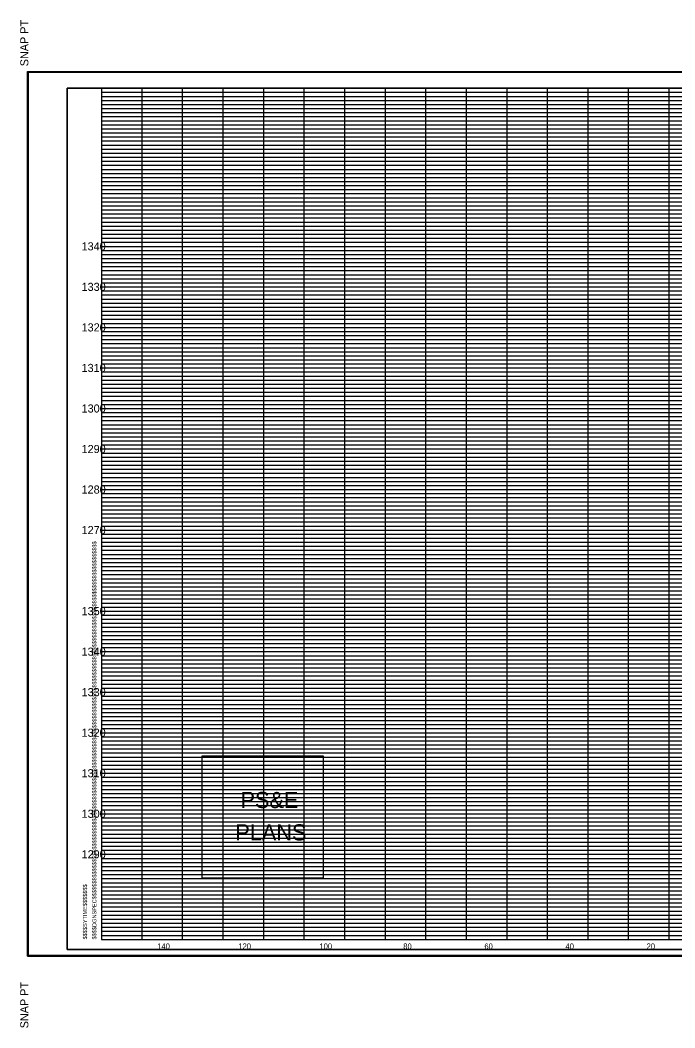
# Model space of a CAD drawing. Extents: x 980 to 1324, y 978 to 2847.
# Drawn here: x 979.9 to 1141.4, y 978.2 to 1226.8 of the extents above; entities that cross this region are included whole.
import ezdxf

# ---------------------------------------------------------------- set-up
doc = ezdxf.new("R2010")
doc.units = 0
for name, color, linetype in [('DESIGN - SHEET - Corner Text', 7, 'Continuous'), ('DESIGN - SHEET - Light Grid', 7, 'Continuous'), ('DESIGN - SHEET - Linework', 7, 'Continuous'), ('DESIGN - SHEET - Plot Shape', 7, 'Continuous'), ('DESIGN - TYPICAL - Text', 7, 'Continuous')]:
    doc.layers.add(name, color=color, linetype=linetype)

# ---------------------------------------------------------------- blocks, each defined once
blk = doc.blocks.new('XSTSHT')
at = {"layer": 'DESIGN - SHEET - Light Grid'}
for p, q in [((0, 20.9), (8, 20.9)), ((8, 20.9), (16, 20.9)), ((0, 20.8), (8, 20.8)), ((0, 20.7), (8, 20.7)), ((8, 20.8), (16, 20.8)), ((8, 20.7), (16, 20.7)), ((0, 20.6), (8, 20.6)), ((0, 20.5), (8, 20.5)), ((0, 20.4), (8, 20.4)), ((8, 20.6), (16, 20.6)), ((8, 20.5), (16, 20.5)), ((8, 20.4), (16, 20.4)), ((0, 20.3), (8, 20.3)), ((0, 20.2), (8, 20.2)), ((8, 20.3), (16, 20.3)), ((8, 20.2), (16, 20.2)), ((0, 20.1), (8, 20.1)), ((0, 19.9), (8, 19.9)), ((8, 20.1), (16, 20.1)), ((8, 19.9), (16, 19.9)), ((0, 19.8), (8, 19.8)), ((0, 19.7), (8, 19.7)), ((8, 19.8), (16, 19.8)), ((8, 19.7), (16, 19.7)), ((0, 19.6), (8, 19.6)), ((0, 19.5), (8, 19.5)), ((0, 19.4), (8, 19.4)), ((8, 19.6), (16, 19.6)), ((8, 19.5), (16, 19.5)), ((8, 19.4), (16, 19.4)), ((0, 19.3), (8, 19.3)), ((0, 19.2), (8, 19.2)), ((8, 19.3), (16, 19.3)), ((8, 19.2), (16, 19.2)), ((0, 19.1), (8, 19.1)), ((0, 18.9), (8, 18.9)), ((8, 19.1), (16, 19.1)), ((8, 18.9), (16, 18.9)), ((0, 18.8), (8, 18.8)), ((0, 18.7), (8, 18.7)), ((8, 18.8), (16, 18.8)), ((8, 18.7), (16, 18.7)), ((0, 18.6), (8, 18.6)), ((0, 18.5), (8, 18.5)), ((0, 18.4), (8, 18.4)), ((8, 18.6), (16, 18.6)), ((8, 18.5), (16, 18.5)), ((8, 18.4), (16, 18.4)), ((0, 18.3), (8, 18.3)), ((0, 18.2), (8, 18.2)), ((8, 18.3), (16, 18.3)), ((8, 18.2), (16, 18.2)), ((0, 18.1), (8, 18.1)), ((8, 18.1), (16, 18.1)), ((0, 17.9), (8, 17.9)), ((0, 17.8), (8, 17.8)), ((0, 17.7), (8, 17.7)), ((8, 17.9), (16, 17.9)), ((8, 17.8), (16, 17.8)), ((8, 17.7), (16, 17.7)), ((0, 17.6), (8, 17.6)), ((0, 17.5), (8, 17.5)), ((8, 17.6), (16, 17.6)), ((8, 17.5), (16, 17.5)), ((0, 17.4), (8, 17.4)), ((0, 17.3), (8, 17.3)), ((0, 17.2), (8, 17.2)), ((8, 17.4), (16, 17.4)), ((8, 17.3), (16, 17.3)), ((8, 17.2), (16, 17.2)), ((0, 17.1), (8, 17.1)), ((8, 17.1), (16, 17.1)), ((0, 16.9), (8, 16.9)), ((0, 16.8), (8, 16.8)), ((0, 16.7), (8, 16.7)), ((8, 16.9), (16, 16.9)), ((8, 16.8), (16, 16.8)), ((8, 16.7), (16, 16.7)), ((0, 16.6), (8, 16.6)), ((0, 16.5), (8, 16.5)), ((8, 16.6), (16, 16.6)), ((8, 16.5), (16, 16.5)), ((0, 16.4), (8, 16.4)), ((0, 16.3), (8, 16.3)), ((0, 16.2), (8, 16.2)), ((8, 16.4), (16, 16.4)), ((8, 16.3), (16, 16.3)), ((8, 16.2), (16, 16.2)), ((0, 16.1), (8, 16.1)), ((8, 16.1), (16, 16.1)), ((0, 15.9), (8, 15.9)), ((0, 15.8), (8, 15.8)), ((0, 15.7), (8, 15.7)), ((8, 15.9), (16, 15.9)), ((8, 15.8), (16, 15.8)), ((8, 15.7), (16, 15.7)), ((0, 15.6), (8, 15.6)), ((0, 15.5), (8, 15.5)), ((8, 15.6), (16, 15.6)), ((8, 15.5), (16, 15.5)), ((0, 15.4), (8, 15.4)), ((0, 15.3), (8, 15.3)), ((0, 15.2), (8, 15.2)), ((8, 15.4), (16, 15.4)), ((8, 15.3), (16, 15.3)), ((8, 15.2), (16, 15.2)), ((0, 15.1), (8, 15.1)), ((8, 15.1), (16, 15.1)), ((0, 14.9), (8, 14.9)), ((0, 14.8), (8, 14.8)), ((0, 14.7), (8, 14.7)), ((8, 14.9), (16, 14.9)), ((8, 14.8), (16, 14.8)), ((8, 14.7), (16, 14.7)), ((0, 14.6), (8, 14.6)), ((0, 14.5), (8, 14.5)), ((8, 14.6), (16, 14.6)), ((8, 14.5), (16, 14.5)), ((0, 14.4), (8, 14.4)), ((0, 14.3), (8, 14.3)), ((0, 14.2), (8, 14.2)), ((8, 14.4), (16, 14.4)), ((8, 14.3), (16, 14.3)), ((8, 14.2), (16, 14.2)), ((0, 14.1), (8, 14.1)), ((8, 14.1), (16, 14.1)), ((0, 13.9), (8, 13.9)), ((0, 13.8), (8, 13.8)), ((0, 13.7), (8, 13.7)), ((8, 13.9), (16, 13.9)), ((8, 13.8), (16, 13.8)), ((8, 13.7), (16, 13.7)), ((0, 13.6), (8, 13.6)), ((0, 13.5), (8, 13.5)), ((8, 13.6), (16, 13.6)), ((8, 13.5), (16, 13.5)), ((0, 13.4), (8, 13.4)), ((0, 13.3), (8, 13.3)), ((0, 13.2), (8, 13.2)), ((8, 13.4), (16, 13.4)), ((8, 13.3), (16, 13.3)), ((8, 13.2), (16, 13.2)), ((0, 13.1), (8, 13.1)), ((8, 13.1), (16, 13.1)), ((0, 12.9), (8, 12.9)), ((0, 12.8), (8, 12.8)), ((0, 12.7), (8, 12.7)), ((8, 12.9), (16, 12.9)), ((8, 12.8), (16, 12.8)), ((8, 12.7), (16, 12.7)), ((0, 12.6), (8, 12.6)), ((0, 12.5), (8, 12.5)), ((8, 12.6), (16, 12.6)), ((8, 12.5), (16, 12.5)), ((0, 12.4), (8, 12.4)), ((0, 12.3), (8, 12.3)), ((0, 12.2), (8, 12.2)), ((8, 12.4), (16, 12.4)), ((8, 12.3), (16, 12.3)), ((8, 12.2), (16, 12.2)), ((0, 12.1), (8, 12.1)), ((8, 12.1), (16, 12.1)), ((0, 11.9), (8, 11.9)), ((0, 11.8), (8, 11.8)), ((0, 11.7), (8, 11.7)), ((8, 11.9), (16, 11.9)), ((8, 11.8), (16, 11.8)), ((8, 11.7), (16, 11.7)), ((0, 11.6), (8, 11.6)), ((0, 11.5), (8, 11.5)), ((8, 11.6), (16, 11.6)), ((8, 11.5), (16, 11.5)), ((0, 11.4), (8, 11.4)), ((0, 11.3), (8, 11.3)), ((0, 11.2), (8, 11.2)), ((8, 11.4), (16, 11.4)), ((8, 11.3), (16, 11.3)), ((8, 11.2), (16, 11.2)), ((0, 11.1), (8, 11.1)), ((8, 11.1), (16, 11.1)), ((0, 10.9), (8, 10.9)), ((0, 10.8), (8, 10.8)), ((0, 10.7), (8, 10.7)), ((8, 10.9), (16, 10.9)), ((8, 10.8), (16, 10.8)), ((8, 10.7), (16, 10.7)), ((0, 10.6), (8, 10.6)), ((0, 10.5), (8, 10.5)), ((8, 10.6), (16, 10.6)), ((8, 10.5), (16, 10.5)), ((0, 10.4), (8, 10.4)), ((0, 10.3), (8, 10.3)), ((0, 10.2), (8, 10.2)), ((8, 10.4), (16, 10.4)), ((8, 10.3), (16, 10.3)), ((8, 10.2), (16, 10.2)), ((0, 10.1), (8, 10.1)), ((8, 10.1), (16, 10.1)), ((0, 9.9), (8, 9.9)), ((0, 9.8), (8, 9.8)), ((0, 9.7), (8, 9.7)), ((8, 9.9), (16, 9.9)), ((8, 9.8), (16, 9.8)), ((8, 9.7), (16, 9.7)), ((0, 9.6), (8, 9.6)), ((0, 9.5), (8, 9.5)), ((8, 9.6), (16, 9.6)), ((8, 9.5), (16, 9.5)), ((0, 9.4), (8, 9.4)), ((0, 9.3), (8, 9.3)), ((0, 9.2), (8, 9.2)), ((8, 9.4), (16, 9.4)), ((8, 9.3), (16, 9.3)), ((8, 9.2), (16, 9.2)), ((0, 9.1), (8, 9.1)), ((8, 9.1), (16, 9.1)), ((0, 8.9), (8, 8.9)), ((0, 8.8), (8, 8.8)), ((8, 8.9), (16, 8.9)), ((8, 8.8), (16, 8.8)), ((0, 8.7), (8, 8.7)), ((0, 8.6), (8, 8.6)), ((0, 8.5), (8, 8.5)), ((8, 8.7), (16, 8.7)), ((8, 8.6), (16, 8.6)), ((8, 8.5), (16, 8.5)), ((0, 8.4), (8, 8.4)), ((0, 8.3), (8, 8.3)), ((8, 8.4), (16, 8.4)), ((8, 8.3), (16, 8.3)), ((0, 8.2), (8, 8.2)), ((0, 8.1), (8, 8.1)), ((8, 8.2), (16, 8.2)), ((8, 8.1), (16, 8.1)), ((0, 7.9), (8, 7.9)), ((0, 7.8), (8, 7.8)), ((8, 7.9), (16, 7.9)), ((8, 7.8), (16, 7.8)), ((0, 7.7), (8, 7.7)), ((0, 7.6), (8, 7.6)), ((0, 7.5), (8, 7.5)), ((8, 7.7), (16, 7.7)), ((8, 7.6), (16, 7.6)), ((8, 7.5), (16, 7.5)), ((0, 7.4), (8, 7.4)), ((0, 7.3), (8, 7.3)), ((8, 7.4), (16, 7.4)), ((8, 7.3), (16, 7.3)), ((0, 7.2), (8, 7.2)), ((0, 7.1), (8, 7.1)), ((8, 7.2), (16, 7.2)), ((8, 7.1), (16, 7.1)), ((0, 6.9), (8, 6.9)), ((0, 6.8), (8, 6.8)), ((8, 6.9), (16, 6.9)), ((8, 6.8), (16, 6.8)), ((0, 6.7), (8, 6.7)), ((0, 6.6), (8, 6.6)), ((0, 6.5), (8, 6.5)), ((8, 6.7), (16, 6.7)), ((8, 6.6), (16, 6.6)), ((8, 6.5), (16, 6.5)), ((0, 6.4), (8, 6.4)), ((0, 6.3), (8, 6.3)), ((8, 6.4), (16, 6.4)), ((8, 6.3), (16, 6.3)), ((0, 6.2), (8, 6.2)), ((0, 6.1), (8, 6.1)), ((8, 6.2), (16, 6.2)), ((8, 6.1), (16, 6.1)), ((0, 5.9), (8, 5.9)), ((0, 5.8), (8, 5.8)), ((8, 5.9), (16, 5.9)), ((8, 5.8), (16, 5.8)), ((0, 5.7), (8, 5.7)), ((0, 5.6), (8, 5.6)), ((0, 5.5), (8, 5.5)), ((8, 5.7), (16, 5.7)), ((8, 5.6), (16, 5.6)), ((8, 5.5), (16, 5.5)), ((0, 5.4), (8, 5.4)), ((0, 5.3), (8, 5.3)), ((8, 5.4), (16, 5.4)), ((8, 5.3), (16, 5.3)), ((0, 5.2), (8, 5.2)), ((0, 5.1), (8, 5.1)), ((8, 5.2), (16, 5.2)), ((8, 5.1), (16, 5.1)), ((0, 4.9), (8, 4.9)), ((0, 4.8), (8, 4.8)), ((8, 4.9), (16, 4.9)), ((8, 4.8), (16, 4.8)), ((0, 4.7), (8, 4.7)), ((0, 4.6), (8, 4.6)), ((0, 4.5), (8, 4.5)), ((8, 4.7), (16, 4.7)), ((8, 4.6), (16, 4.6)), ((8, 4.5), (16, 4.5)), ((0, 4.4), (8, 4.4)), ((0, 4.3), (8, 4.3)), ((8, 4.4), (16, 4.4)), ((8, 4.3), (16, 4.3)), ((0, 4.2), (8, 4.2)), ((0, 4.1), (8, 4.1)), ((8, 4.2), (16, 4.2)), ((8, 4.1), (16, 4.1)), ((0, 3.9), (8, 3.9)), ((0, 3.8), (8, 3.8)), ((8, 3.9), (16, 3.9)), ((8, 3.8), (16, 3.8)), ((0, 3.7), (8, 3.7)), ((0, 3.6), (8, 3.6)), ((0, 3.5), (8, 3.5)), ((8, 3.7), (16, 3.7)), ((8, 3.6), (16, 3.6)), ((8, 3.5), (16, 3.5)), ((0, 3.4), (8, 3.4)), ((0, 3.3), (8, 3.3)), ((8, 3.4), (16, 3.4)), ((8, 3.3), (16, 3.3)), ((0, 3.2), (8, 3.2)), ((0, 3.1), (8, 3.1)), ((8, 3.2), (16, 3.2)), ((8, 3.1), (16, 3.1)), ((0, 2.9), (8, 2.9)), ((0, 2.8), (8, 2.8)), ((8, 2.9), (16, 2.9)), ((8, 2.8), (16, 2.8)), ((0, 2.7), (8, 2.7)), ((0, 2.6), (8, 2.6)), ((0, 2.5), (8, 2.5)), ((8, 2.7), (16, 2.7)), ((8, 2.6), (16, 2.6)), ((8, 2.5), (16, 2.5)), ((0, 2.4), (8, 2.4)), ((0, 2.3), (8, 2.3)), ((8, 2.4), (16, 2.4)), ((8, 2.3), (16, 2.3)), ((0, 2.2), (8, 2.2)), ((0, 2.1), (8, 2.1)), ((8, 2.2), (16, 2.2)), ((8, 2.1), (16, 2.1)), ((0, 1.9), (8, 1.9)), ((0, 1.8), (8, 1.8)), ((8, 1.9), (16, 1.9)), ((8, 1.8), (16, 1.8)), ((0, 1.7), (8, 1.7)), ((0, 1.6), (8, 1.6)), ((0, 1.5), (8, 1.5)), ((8, 1.7), (16, 1.7)), ((8, 1.6), (16, 1.6)), ((8, 1.5), (16, 1.5)), ((0, 1.4), (8, 1.4)), ((0, 1.3), (8, 1.3)), ((8, 1.4), (16, 1.4)), ((8, 1.3), (16, 1.3)), ((0, 1.2), (8, 1.2)), ((0, 1.1), (8, 1.1)), ((8, 1.2), (16, 1.2)), ((8, 1.1), (16, 1.1)), ((0, 0.9), (8, 0.9)), ((0, 0.8), (8, 0.8)), ((8, 0.9), (16, 0.9)), ((8, 0.8), (16, 0.8)), ((0, 0.7), (8, 0.7)), ((0, 0.6), (8, 0.6)), ((0, 0.5), (8, 0.5)), ((8, 0.7), (16, 0.7)), ((8, 0.6), (16, 0.6)), ((8, 0.5), (16, 0.5)), ((0, 0.4), (8, 0.4)), ((0, 0.3), (8, 0.3)), ((8, 0.4), (16, 0.4)), ((8, 0.3), (16, 0.3)), ((0, 0.2), (8, 0.2)), ((0, 0.1), (8, 0.1)), ((8, 0.2), (16, 0.2)), ((8, 0.1), (16, 0.1))]:
    blk.add_line(p, q, dxfattribs=at)
at = {"layer": 'DESIGN - SHEET - Linework'}
for p, q in [((-1.823, -0.414), (-1.823, 21.414)), ((-1.823, 21.414), (32.217, 21.414)), ((1, 0), (1, 21)), ((2, 0), (2, 21)), ((3, 0), (3, 21)), ((4, 0), (4, 21)), ((5, 0), (5, 21)), ((6, 0), (6, 21)), ((7, 0), (7, 21)), ((8, 0), (8, 21)), ((9, 0), (9, 21)), ((10, 0), (10, 21)), ((11, 0), (11, 21)), ((12, 0), (12, 21)), ((13, 0), (13, 21)), ((14, 0), (14, 21)), ((0, 20), (28, 20)), ((0, 19), (32, 19)), ((0, 18), (32, 18)), ((0, 17), (32, 17)), ((0, 16), (32, 16)), ((0, 15), (32, 15)), ((0, 14), (32, 14)), ((0, 13), (32, 13)), ((0, 12), (32, 12)), ((0, 11), (32, 11)), ((0, 10), (32, 10)), ((0, 9), (32, 9)), ((0, 8), (32, 8)), ((0, 7), (32, 7)), ((0, 6), (32, 6)), ((0, 5), (32, 5)), ((0, 4), (32, 4)), ((0, 3), (32, 3)), ((0, 2), (32, 2)), ((0, 1), (32, 1)), ((-1.823, -0.414), (32.217, -0.414))]:
    blk.add_line(p, q, dxfattribs=at)
blk.add_lwpolyline([(0, 21), (0, 0), (32, 0), (32, 21), (0, 21)], dxfattribs=at)
at = {"layer": 'DESIGN - SHEET - Plot Shape'}
for points in [[(-1.803, 21.394), (32.197, 21.394), (32.197, -0.394), (-1.803, -0.394)], [(-0.85, 21), (32, 21), (32, -0.25), (-0.85, -0.25)]]:
    blk.add_lwpolyline(points, close=True, dxfattribs=at)
at = {"layer": 'DESIGN - SHEET - Corner Text'}
for s, height, p in [('  SNAP PT', 0.2, (-1.803, 21.394)), ('$$$$DGNSPEC$$$$$$$$$$$$$$$$$$$$$$$$$$$$$$$$$$$$$$$$$$$$$$$$$$$$$$$$$$$$$$$$$$$$$$$$$$$$$$$$$$$$$$$$$$$$$$$$$$$$$$$$$$$$$$$$$$$', 0.100002, (-0.126, 0)), ('$$$$SYTIME$$$$$$$', 0.1, (-0.358, 0)), ('SNAP PT  ', 0.2, (-1.803, -2.194))]:
    blk.add_text(s, height=height, rotation=90, dxfattribs=at).set_placement(p)

msp = doc.modelspace()

# ---------------------------------------------------------------- linework, layer by layer
at = {"layer": 'DESIGN - SHEET - Corner Text'}
msp.add_lwpolyline([(1024.78, 1045.23), (1024.78, 1015.23), (1054.78, 1015.23), (1054.78, 1045.23)], close=True, dxfattribs=at)
at = {"layer": 'DESIGN - SHEET - Plot Shape'}
msp.add_lwpolyline([(991.5, 997.5), (1320, 997.5), (1320, 1210), (991.5, 1210)], close=True, dxfattribs=at)

# ---------------------------------------------------------------- block references
at = {"layer": 'DESIGN - SHEET - Plot Shape', "xscale": 10, "yscale": 10}
msp.add_blockref('XSTSHT', (1000, 1000), dxfattribs=at)

# ---------------------------------------------------------------- texts
at = {"layer": 'DESIGN - SHEET - Corner Text'}
for s, p in [('PS&E', (1034.29, 1032.41)), ('PLANS', (1033.01, 1024.41))]:
    msp.add_text(s, height=4, dxfattribs=at).set_placement(p)
at = {"layer": 'DESIGN - TYPICAL - Text'}
for s, height, p in [('     1340     ', 2, (991.37, 1170)), ('     1330     ', 2, (991.37, 1160)), ('     1320     ', 2, (991.37, 1150)), ('     1310     ', 2, (991.37, 1140)), ('     1300     ', 2, (991.37, 1130)), ('     1290     ', 2, (991.37, 1120)), ('     1280     ', 2, (991.37, 1110)), ('     1270     ', 2, (991.37, 1100)), ('     1350     ', 2, (991.37, 1080)), ('     1340     ', 2, (991.37, 1070)), ('     1330     ', 2, (991.37, 1060)), ('     1320     ', 2, (991.37, 1050)), ('     1310     ', 2, (991.37, 1040)), ('     1300     ', 2, (991.37, 1030)), ('     1290     ', 2, (991.37, 1020)), ('     140     ', 1.4, (1011.14, 997.6)), ('     120     ', 1.4, (1031.14, 997.6)), ('     100     ', 1.4, (1051.14, 997.6)), ('     80     ', 1.4, (1071.82, 997.6)), ('     60     ', 1.4, (1091.82, 997.6)), ('     40     ', 1.4, (1111.82, 997.6)), ('     20     ', 1.4, (1131.82, 997.6))]:
    msp.add_text(s, height=height, dxfattribs=at).set_placement(p)

doc.saveas('drawing.dxf')
